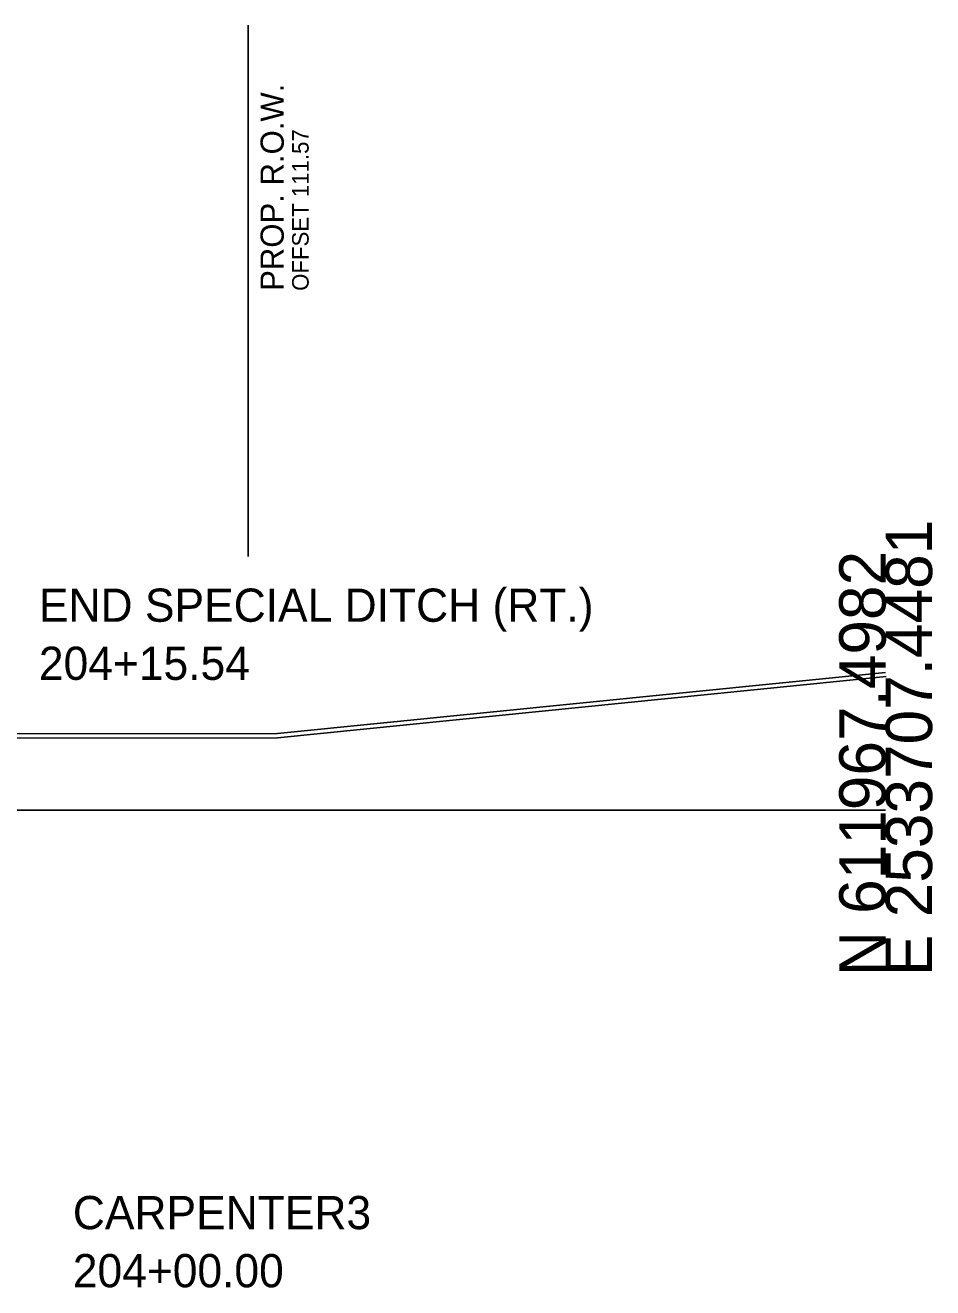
# Model space of a CAD drawing. Extents: x -120 to 2876, y -25 to 8560.
# Drawn here: x 248.1 to 302.8, y 7471.2 to 7547.3 of the extents above; entities that cross this region are included whole.
import ezdxf

# ---------------------------------------------------------------- set-up
doc = ezdxf.new("R2010")
doc.units = 0
for name, color, linetype in [('DESIGN - ROW - Right-of-Way and Easement Labels', 7, 'Continuous'), ('DESIGN - ROW - Right-of-Way Linework', 7, 'Continuous'), ('DESIGN - SHEET - Light Grid', 7, 'Continuous'), ('DESIGN - TRANSPORTATION - Text', 7, 'Continuous'), ('DESIGN - TYPICAL - Warning Text', 7, 'Continuous'), ('SURVEY - GROUND - Bottom of Topsoil Layer', 7, 'Continuous'), ('SURVEY - GROUND - Top of Ground', 7, 'Continuous')]:
    doc.layers.add(name, color=color, linetype=linetype)

msp = doc.modelspace()

# ---------------------------------------------------------------- linework, layer by layer
at = {"layer": 'DESIGN - ROW - Right-of-Way Linework'}
msp.add_line((261.567, 7515.273), (261.567, 7547.273), dxfattribs=at)
at = {"layer": 'DESIGN - SHEET - Light Grid'}
msp.add_line((150, 7500), (300, 7500), dxfattribs=at)
at = {"layer": 'SURVEY - GROUND - Bottom of Topsoil Layer'}
msp.add_lwpolyline([(180.696, 7513.309), (190.852, 7506.545), (198.837, 7501.508), (200.117, 7500.814), (205.914, 7500.797), (206.44, 7500.772), (210.929, 7504.127), (213.045, 7504.25), (216.507, 7504.337), (263.344, 7504.356), (300.025, 7508.038)], dxfattribs=at)
at = {"layer": 'SURVEY - GROUND - Top of Ground'}
msp.add_lwpolyline([(163.787, 7514.662), (171.546, 7514.298), (173.6, 7514.203), (177.329, 7513.981), (180.71, 7513.6), (190.988, 7506.755), (198.963, 7501.724), (200.181, 7501.064), (205.92, 7501.047), (206.362, 7501.026), (210.839, 7504.372), (213.035, 7504.5), (216.503, 7504.587), (263.331, 7504.606), (300, 7508.286)], dxfattribs=at)

# ---------------------------------------------------------------- texts
at = {"layer": 'DESIGN - ROW - Right-of-Way and Easement Labels'}
for s, height, p in [('PROP. R.O.W.', 1.4, (263.717, 7531.273)), ('OFFSET 111.57', 1, (265.217, 7531.273))]:
    msp.add_text(s, height=height, rotation=90, dxfattribs=at).set_placement(p)
at = {"layer": 'DESIGN - SHEET - Light Grid'}
for s, p in [('E 2533707.4481', (302.8, 7490)), ('N 611967.4982', (300, 7490))]:
    msp.add_text(s, height=2.8, rotation=90, dxfattribs=at).set_placement(p)
at = {"layer": 'DESIGN - TRANSPORTATION - Text'}
for s, p in [('END SPECIAL DITCH (RT.)', (248.955, 7511.339)), ('204+15.54', (248.955, 7507.839))]:
    msp.add_text(s, height=2, dxfattribs=at).set_placement(p)
at = {"layer": 'DESIGN - TYPICAL - Warning Text'}
for s, p in [('CARPENTER3', (251, 7474.75)), ('204+00.00', (251, 7471.25))]:
    msp.add_text(s, height=2, dxfattribs=at).set_placement(p)

doc.saveas('drawing.dxf')
